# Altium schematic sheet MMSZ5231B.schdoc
size 127 x 101 mm
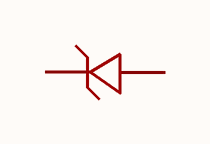
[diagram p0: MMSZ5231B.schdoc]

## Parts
ZD?  mmsz5231b  [SOD-123_L2.8-W1.8-LS3.7-RD]  (value not drawn)

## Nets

Not connected (* = marked no-connect by the designer): ZD? 1(K) 2(A)

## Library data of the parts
ZD? = mmsz5231b: 二极管配置:1个独立式;稳压值(标称值):5.1V;稳压值(范围):4.85V~5.36V;耗散功率(Pd):500mW;; Manufacturer: CJ(江苏长电/长晶); AddInBom: yes; ModelId: 7884390a25fb4c08947731ebfba7e3f8; ModelTransform: 144.8816,62.992,0,0,0,0,0,0,0; Diode Configuration: 1个独立式; Zener Voltage(Nom): 5.1V; Reverse Leakage Current (Ir): 5uA@2V; Pd - Power Dissipation: 500mW; Impedance(Zzt): 17Ω; Impedance(Zzk): 1.6kΩ; Operating Junction Temperature Range: -55℃~+150℃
